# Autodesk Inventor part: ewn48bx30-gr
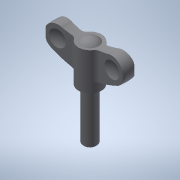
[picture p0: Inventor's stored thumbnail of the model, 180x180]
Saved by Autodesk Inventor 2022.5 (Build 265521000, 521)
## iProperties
Created: 2017-05
Part Number: ewn48bx30-gr
Material: 一般
Document SubType Name: Modeling
Designer: imaocorp
Density: 1 g/cm^3
Appearance: 既定
Author: imaocorp
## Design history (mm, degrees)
node "ewn48bx30-gr.x_t1"
node "ewn48bx30-gr"
node "Base1"
